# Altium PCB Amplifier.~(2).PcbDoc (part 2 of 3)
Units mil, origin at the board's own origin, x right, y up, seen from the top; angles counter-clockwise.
Board outline 9055.12 x 4724.41 mil, 2 copper layers (Top Layer, Bottom Layer); 154 components, 83 nets, 405 pads, 1525 vias.
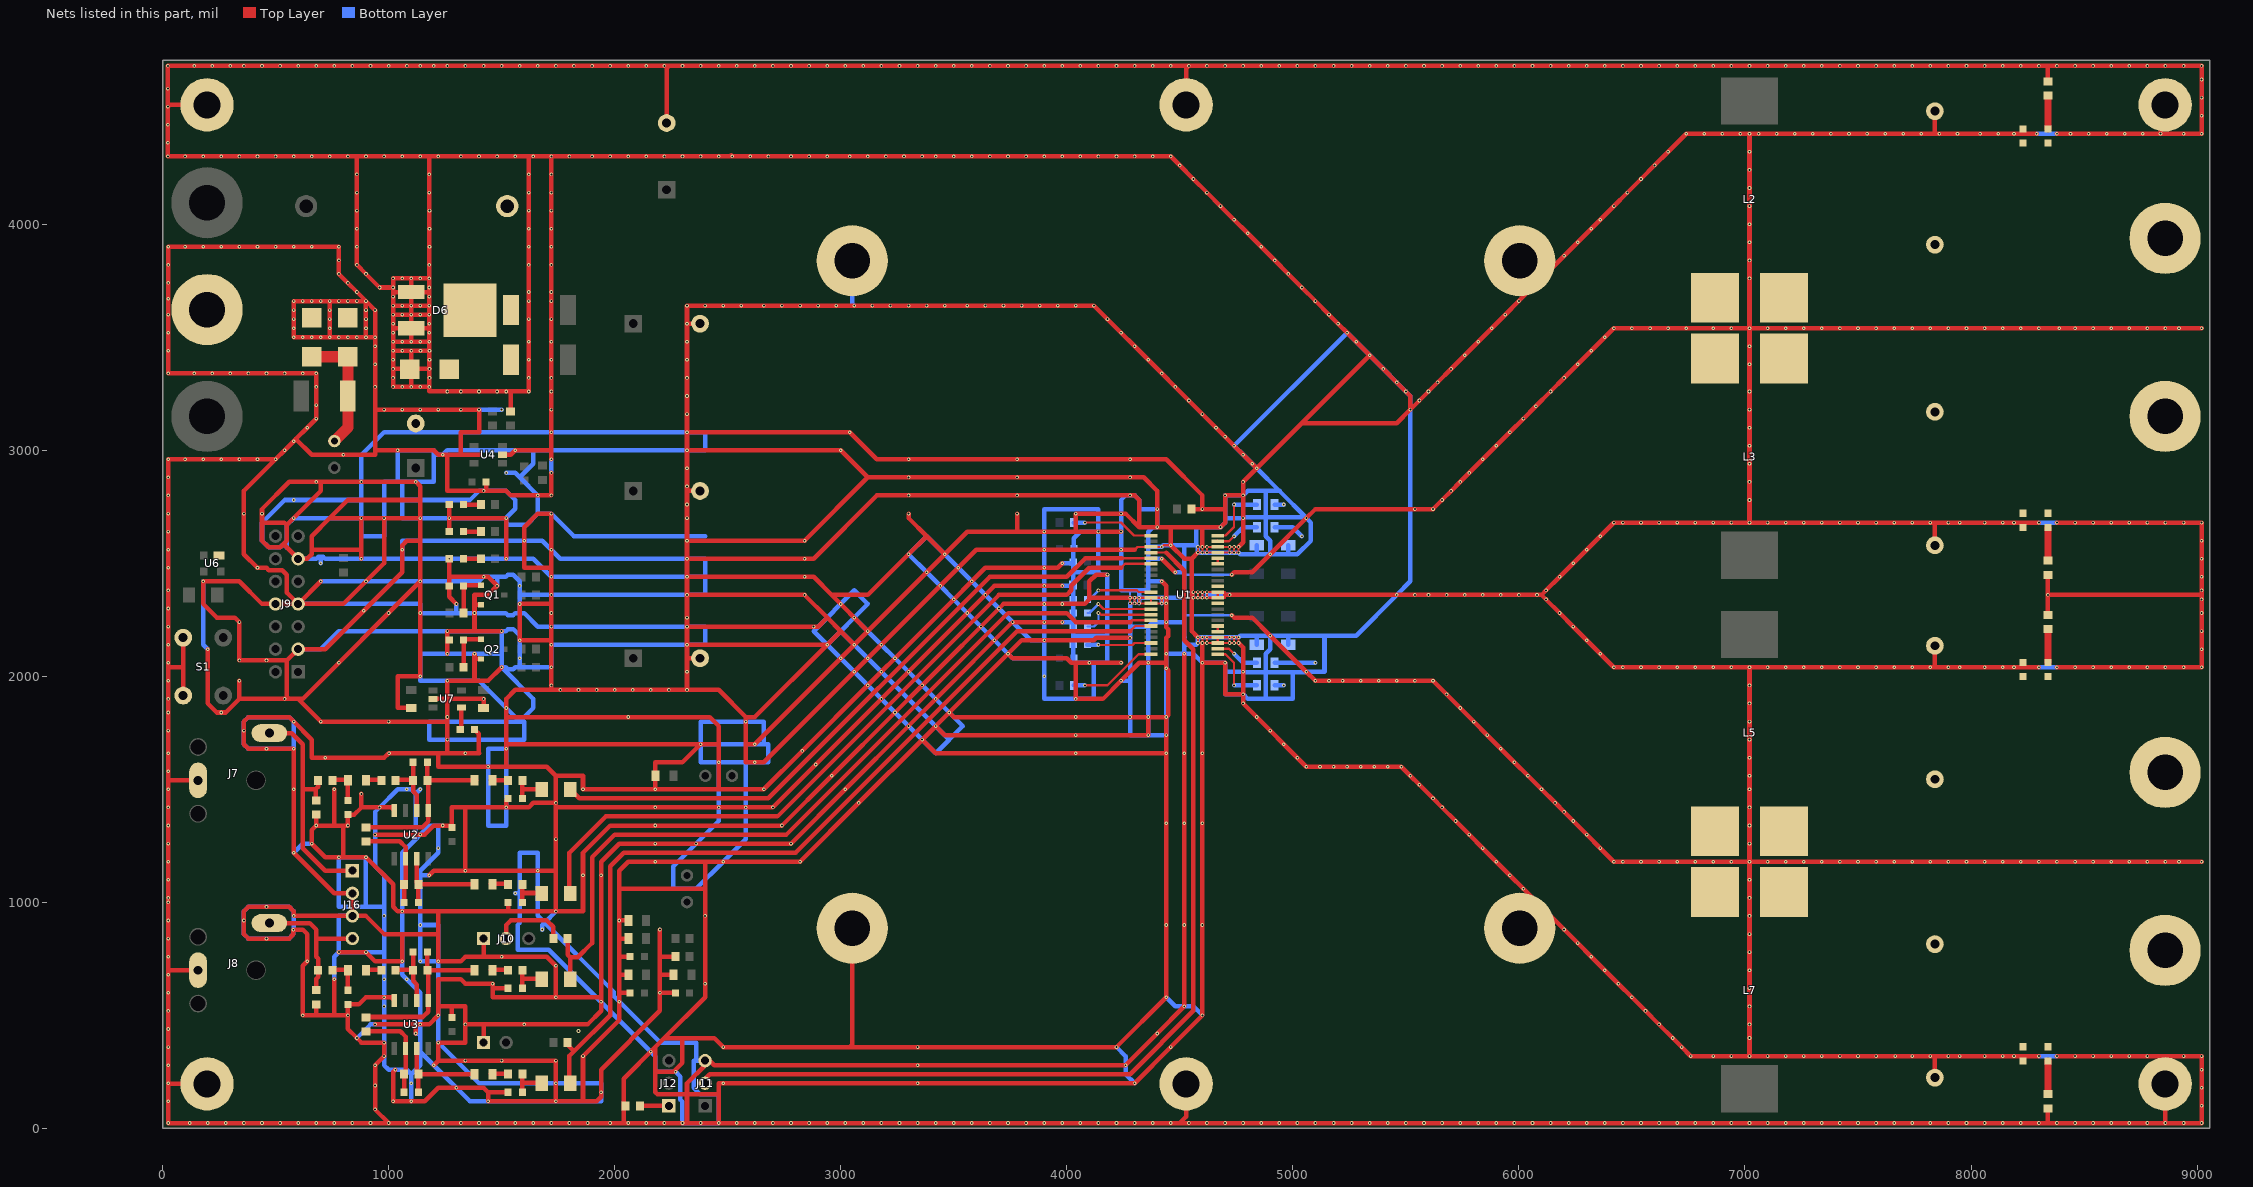
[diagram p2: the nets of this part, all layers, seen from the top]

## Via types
v1: diameter 15.75, hole 7.87, Top Layer to Bottom Layer, 1525 vias

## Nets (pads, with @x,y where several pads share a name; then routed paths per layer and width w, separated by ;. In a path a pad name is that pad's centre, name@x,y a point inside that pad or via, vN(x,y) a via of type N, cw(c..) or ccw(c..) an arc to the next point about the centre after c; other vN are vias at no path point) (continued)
GND: C4.2 C5.2 C6.2 C7.2 C8.2 C9.2 C10.2 C13.2 C14.2 C16.2 C17.2 C20.2 C21.2 C24.2 C25.2 C26.2 C28.2 C29.2 C30.2 C32.2 C33.2 C34.2 C35.2 C36.2 C37.2 C38.2 C39.2 C42.2 C44.1 C45.2 C46.2 C49.1 C50.2 C54.2 C55.2 C59.2 C60.2 C63.2 C65.2 C67.1 C68.2 C69.2 C72.2 C73.2 D1.2 D2.2 D3.2 D4.2 D5.2 D6.1 D6.3 D7.1 D8.1 D9.1 J2.1 J7.1 J8.1 J9.3 J9.7 J9.8 J9.11 J10.1 J11.3 J14.1 J16.2 J16.3 pad. Q1.3 Q2.3 R17.2 R25.2 R34.2 R39.2 R41.2 R46.2 R49.1 R51.2 R55.2 R57.1 R60.1 S1.1 U1.3 U1.12 U1.13 U1.25 U1.26 U1.33 U1.34 U1.41 U1.42 U2.4 U3.4 U4.2 U6.1 U7.2 | length 233486.2
  Top Layer w10: D5.2@1260,2528.5 v1(1268.5,2520) ; D4.2@1260,2648.5 D4.2@1268.5,2640 ; D3.2@1260,2751.5 D3.2@1268.5,2760 ; 4300,2560 4312.5,2572.5 U1.3@4372.36,2572.5 v1(4420,2572.5) 4427.5,2580 v1(4460,2580) ; v1(4440,2322.5) v1(4420,2322.5) ; v1(4440,2347.5) v1(4420,2347.5) ; v1(4300,2322.5) v1(4280,2322.5) v1(4280,2347.5) v1(4300,2347.5) ; v1(4300,2322.5) v1(4320,2322.5) ; v1(4300,2322.5) v1(4300,2347.5) ; v1(4300,2347.5) v1(4320,2347.5) ; v1(4320,2322.5) U1.13@4372.36,2322.5 ; v1(4320,2322.5) v1(4320,2347.5) ; v1(4320,2347.5) U1.12@4372.36,2347.5 ; U1.13@4372.36,2322.5 v1(4420,2322.5) ; U1.13@4372.36,2322.5 U1.12@4372.36,2347.5 ; U1.12@4372.36,2347.5 v1(4420,2347.5) ; v1(4420,2322.5) v1(4420,2347.5) ; v1(4580,2347.5) v1(4560,2347.5) v1(4560,2372.5) v1(4580,2372.5) ; v1(4580,2347.5) v1(4600,2347.5) ; v1(4580,2347.5) v1(4580,2372.5) ; v1(4580,2372.5) v1(4600,2372.5) ; v1(4600,2147.5) v1(4600,2172.5) ; v1(4600,2147.5) v1(4620,2147.5) ; v1(4600,2147.5) v1(4580,2147.5) v1(4580,2172.5) v1(4600,2172.5) ; v1(4600,2172.5) v1(4620,2172.5) ; v1(4600,2347.5) v1(4600,2372.5) ; v1(4600,2347.5) v1(4620,2347.5) ; v1(4600,2372.5) v1(4620,2372.5) ; v1(4600,2547.5) v1(4600,2572.5) ; v1(4600,2547.5) v1(4620,2547.5) ; v1(4600,2547.5) v1(4580,2547.5) v1(4580,2572.5) v1(4600,2572.5) ; v1(4600,2572.5) v1(4620,2572.5) ; v1(4620,2147.5) U1.25@4667.64,2147.5 ; v1(4620,2147.5) v1(4620,2172.5) ; v1(4620,2172.5) U1.26@4667.64,2172.5 ; v1(4620,2347.5) U1.33@4667.64,2347.5 ; v1(4620,2347.5) v1(4620,2372.5) ; v1(4620,2372.5) U1.34@4667.64,2372.5 ; v1(4620,2547.5) U1.41@4667.64,2547.5 v1(4720,2547.5) ; v1(4620,2547.5) v1(4620,2572.5) ; v1(4620,2572.5) U1.42@4667.64,2572.5 v1(4720,2572.5) ; U1.25@4667.64,2147.5 U1.26@4667.64,2172.5 ; U1.25@4667.64,2147.5 v1(4720,2147.5) ; U1.26@4667.64,2172.5 v1(4720,2172.5) ; U1.33@4667.64,2347.5 U1.34@4667.64,2372.5 ; U1.33@4667.64,2347.5 4700,2347.5 4700,2360 4700,2372.5 U1.34@4667.64,2372.5 ; v1(4720,2147.5) v1(4740,2147.5) ; v1(4720,2147.5) v1(4720,2172.5) ; v1(4720,2172.5) v1(4740,2172.5) ; v1(4720,2547.5) v1(4740,2547.5) ; v1(4720,2547.5) v1(4720,2572.5) ; v1(4720,2572.5) v1(4740,2572.5) ; v1(4740,2147.5) v1(4740,2172.5) ; v1(4740,2147.5) v1(4760,2147.5) v1(4760,2172.5) v1(4740,2172.5) ; v1(4740,2547.5) v1(4740,2572.5) ; v1(4740,2547.5) v1(4760,2547.5) v1(4760,2572.5) v1(4740,2572.5)
  Top Layer w20: S1.1@91.42,1915.1 91.42,2040 ; S1.1@91.42,2171 91.42,2040 ; J8.1@157.48,700 25.58,700 ; J7.1@157.48,1540 25.58,1540 ; pad.@193.7,200 pad.@196.85,196.85 28.73,196.85 v1(25.58,200) ; pad.@196.85,4527.56 31.56,4527.56 v1(24,4520) ; v1(200,2120) 200,1880 240,1840 280,1840 340,1900 ; v1(340,1980) 340,1900 ; R34.2@680,548.5 680,500 ; R17.2@680,1388.5 v1(680,1340) ; v1(700,2420) J9.7@600,2320 ; v1(760,660) 760,500 ; v1(760,1500) 760,1340 ; v1(780,780) v1(900,780) 940,740 v1(1060,740) 1060,860 ; v1(880,1480) 880,1420 ; v1(880,2520) 880,2560 ; v1(900,3500) v1(900,3660) ; v1(940,460) 1120,460 ; v1(940,1300) v1(1140,1300) 1160,1300 1200,1340 v1(1240,1340) 1271.5,1340 C5.2@1280,1331.5 ; v1(1020,3680) v1(1020,3640) ; U3.4@1025,566.3 1011.3,580 v1(980,580) 900,580 868.5,548.5 C24.2@820,548.5 v1(820,500) ; U2.4@1025,1406.3 1011.3,1420 v1(960,1420) 880,1420 ; v1(1030,260) 1020,250 v1(1020,120) v1(1100,120) 1160,120 1220,180 v1(1300,180) 1420,180 1440,160 ; C72.2@1100,1860.63 1099.37,1860 1040,1860 1040,2000 v1(1140,2000) v1(1140,2280) v1(1140,2420) ; v1(1120,420) 1120,460 ; 1139.5,2638.5 1139.5,2620 1140,2619.5 1140,2600 ; 1139.5,2640 v1@1139.5,2700 ; v1(1140,2700) v1@1139.5,2700 ; 1140,2780 820,2780 740,2700 ; v1(1180,1120) 1200,1140 v1(1340,1140) ; 1180,4300 v1(1180,3820) v1(1180,3760) ; v1(1181.01,3360) v1@1180,3360 ; U7.2@1197.01,1900 1260,1900 ; v1(1200,280) 1220,300 ; 1220,320 1220,300 ; 1259.84,2980 1259.84,2820 v1(1420,2820) 1520,2820 1540,2800 v1(1660,2800) v1(1720,2800) v1(1720,2900) ; v1(1260,2100) v1(1260,2200) 1380,2200 ; v1(1268.5,2520) 1268.5,2440 ; D4.2@1268.5,2640 v1(1268.5,2700) ; D3.2@1268.5,2760 v1(1268.5,2700) ; C21.2@1280,491.5 1280,540 ; C5.2@1280,1340 1280,1420 1340,1420 ; v1(1300,2320) 1268.5,2351.5 D1.2@1268.5,2400 1268.5,2440 ; v1(1380,2100) 1380,2076.69 ; C30.2@1380.04,1765 1399.37,1745.67 1399.37,1660.63 1400,1660 v1(1340,1660) 1260,1660 ; 1400,2980 1320,2980 ; Q2.3@1408.82,2076.69 1380,2076.69 ; Q1.3@1408.82,2316.69 1380,2316.69 ; J14.1@1420,380 1420,460 ; J10.1@1420,840 1420,760 ; C73.2@1420,1860.63 v1(1420,1900) 1260,1900 ; 1431.5,2828.5 C26.2@1431.5,2860 ; v1(1500,2040) 1440,1980 1380,1980 ; v1(1500,2200) 1380,2200 ; U4.2@1502.99,2980 1540,2980 v1(1560,3000) 1720,3000 ; v1(1520,2520) v1(1520,2700) v1(1268.5,2700) ; C25.2@1528.5,160 1440,160 ; C20.2@1528.5,620 1460,620 ; C14.2@1528.5,1000 1528.5,968.5 1520,960 ; C4.2@1528.5,1460 1520,1451.5 v1(1520,1420) ; R39.2@1540,3171.5 1540,3260 ; v1(1720,2960) 1720,3000 ; 1740,1420 v1(2180,1420) v1(2700,1420) v1(2890,1610) v1(3180,1900) v1(3300,2020) 3680,2400 v1(3900,2400) v1(3980,2400) ; 2040,24 2040,220 2180,360 ; C9.2@2060.63,680 2020,680 ; C7.2@2060.63,840 2020,840 ; C6.2@2060.63,920 v1(2020,920) ; C10.2@2068.5,600 2020,600 ; C8.2@2068.5,760 2020,760 ; C59.2@2180.63,1560 C59.2@2180,1559.37 ; v1(2200,880) 2200,760 ; C32.2@2230,4447.64 2230,4690 2240,4700 ; C16.2@2260.63,680 2200,680 ; C17.2@2268.5,600 v1(2200,600) ; R25.2@2268.5,760 2200,760 ; C33.2@2377.64,2080 2320,2080 ; C34.2@2377.64,2820 2320,2820 ; C35.2@2377.64,3560 v1(2320,3560) ; J11.3@2380,300 J11.3@2400,300 ; v1@2515.43,4304.57 v1(2520,4300) ; pad.@3045.35,880 pad.@3051.18,885.83 3051.18,371.18 3040,360 ; pad.@3051.18,3838.58 pad.@3060,3847.4 ; v1(3300,2720) 3300,2700 3380,2620 ; v1(3420,1780) 3460,1740 v1(4040,1740) v1(4360,1740) v1(4360,1820) ; v1(3780,2720) 3780,2640 ; v1(3980,2240) v1(3900,2240) v1(3760,2240) v1(3420,1900) v1(3300,1780) v1(3020,1500) v1(2780,1260) v1(2180,1260) 2020,1260 1940,1180 1940,580 ; v1(3980,2500) 3960,2480 v1(3900,2480) 3640,2480 v1(3580,2420) v1(3500,2340) v1(3240,2080) v1(3180,2020) v1(3120,1960) v1(2830,1670) v1(2660,1500) 2460,1500 ; v1(4180,2450) 4130,2450 4100,2420 4100,2340 ; v1(4240,2060) v1(4100,2060) 4040,2060 ; v1(4240,2640) v1(4140,2640) 4040,2640 ; v1(4280,2170) 4130,2170 4120,2160 v1(3901.01,2160) 3800,2160 v1(3740,2100) ; v1(4280,2347.5) 4279.63,2347.87 4107.87,2347.87 4100,2340 ; 4300,2560 v1(4240,2560) v1(3900,2560) 3600,2560 v1(3520,2480) v1(3440,2400) v1(3180,2140) v1(3120,2080) v1(3060,2020) 2660,1620 v1(2620,1620) 2580,1620 2580,1700 ; v1(4420,2420) 4440,2400 v1(4440,2347.5) v1(4440,2322.5) v1(4440,2240) 4440,2216.92 4447.87,2209.05 4447.87,2178.08 4440,2170.21 v1(4440,2100) 4440,2060 ; v1(4420,2520) v1(4480,2460) ; pad.@4460,4460 pad.@4527.56,4527.56 4527.56,4687.56 v1(4540,4700) ; pad.@4503.15,196.85 pad.@4527.56,196.85 4527.56,51.56 4500,24 ; v1(4520,2100) v1(4520,1350) v1(4520,900) v1(4520,540) v1(4400,420) v1(4260,280) v1(3340,280) 2440,280 2420,300 J11.3@2400,300 ; R60.1@4551.5,2740 v1(4600,2740) ; v1(4580,2172.5) 4552.13,2200.37 4552.13,2519.63 ; v1(4580,2547.5) 4552.13,2519.63 ; v1(4600,2147.5) v1(4600,2060) ; v1(4600,2572.5) 4600,2660 ; 4700,2360 v1(4720,2360) v1(5460,2360) v1(5540,2360) v1(5600,2360) v1(5680,2360) v1(5760,2360) v1(5840,2360) v1(5920,2360) v1(6000,2360) v1(6080,2360) 6100,2360 ; v1(4730,2270) 4740,2260 4820,2260 v1(4900,2180) v1(5060,2020) v1(5100,1980) v1(5160,1980) v1(5220,1980) v1(5300,1980) v1(5380,1980) v1(5460,1980) v1(5540,1980) v1(5620,1980) v1(5680,1920) v1(5740,1860) v1(5800,1800) v1(5860,1740) v1(5920,1680) v1(5980,1620) v1(6040,1560) v1(6100,1500) v1(6160,1440) v1(6200,1400) v1(6240,1360) v1(6300,1300) v1(6360,1240) v1(6420,1180) v1(6460,1180) v1(6540,1180) v1(6620,1180) v1(6700,1180) v1(6780,1180) v1(6860,1180) v1(6940,1180) v1(7020,1180) ; v1(4730,2450) 4740,2460 4820,2460 v1(4900,2540) v1(5060,2700) 5100,2740 v1(5540,2740) v1(5620,2740) v1(5660,2780) v1(5700,2820) v1(5740,2860) v1(5780,2900) v1(5840,2960) v1(5900,3020) v1(5960,3080) v1(6020,3140) v1(6075,3195) v1(6140,3260) v1(6200,3320) v1(6260,3380) v1(6320,3440) v1(6380,3500) v1(6420,3540) v1(6500,3540) v1(6580,3540) v1(6660,3540) v1(6740,3540) v1(6860,3540) v1(6940,3540) v1(7020,3540) ; v1(4760,2147.5) 4780,2127.5 v1(4780,2020) v1(4780,1920) ; v1(4760,2572.5) 4780,2592.5 v1(4780,2700) v1(4780,2800) ; pad.@6003.94,885.83 6005.83,885.83 pad.@6100,980 ; v1@7815,2040 v1(7740,2040) v1(7660,2040) v1(7580,2040) v1(7500,2040) v1(7420,2040) v1(7340,2040) v1(7260,2040) v1(7180,2040) v1(7100,2040) v1(7020,2040) ; v1(7820,2040) 7840,2040 ; C68.2@7840,224.72 7840,320 ; C54.2@7840,2160 C54.2@7840,2135.28 7840,2040 ; C28.2@7840,4500 7840,4400 ; C45.2@7840.28,2579.72 7840.28,2680 ; v1(8290,4400) v1(8190,4400) v1(8120,4400) v1(8040,4400) v1(7940,4400) v1(7860,4400) 7840,4400 ; v1(8300,320) v1(8190,320) v1(8140,320) v1(8060,320) v1(7950,320) v1(7900,320) 7840,320 ; v1(8300,2040) v1(8190,2040) v1(8140,2040) v1(8060,2040) v1(7950,2040) v1(7900,2040) 7840,2040 ; v1(8300,2680) v1(8190,2680) v1(8140,2680) v1(8060,2680) v1(7950,2680) v1(7900,2680) 7840.28,2680 ; R55.2@8340,88.5 8340,24 ; R51.2@8340,2280 v1(8340,2360) ; R46.2@8340,2448.5 v1(8340,2360) ; R41.2@8340,4631.5 8340,4700 ; v1(8380,320) v1(8460,320) v1(8540,320) v1(8620,320) v1(8700,320) v1(8780,320) v1(8940,320) v1(9020,320) v1(9020,260) v1(9020,180) v1(9020,100) v1(9020,24) v1(8940,24) v1(8860,24) ; v1(8380,2040) v1(8460,2040) v1(8540,2040) v1(8620,2040) v1(8700,2040) v1(8780,2040) v1(8860,2040) v1(8940,2040) v1(9020,2040) v1(9020,2120) v1(9020,2200) v1(9020,2280) v1(9020,2340) 9020,2360 ; v1(8380,2680) v1(8460,2680) v1(8540,2680) v1(8620,2680) v1(8700,2680) v1(8780,2680) v1(8860,2680) v1(8940,2680) v1(9020,2680) v1(9020,2600) v1(9020,2520) v1(9020,2440) v1(9020,2380) 9020,2360 ; v1(8380,4400) v1(8440,4400) v1(8520,4400) v1(8600,4400) v1(8680,4400) v1(8760,4400) v1(8940,4400) v1(9020,4400) v1(9020,4480) v1(9020,4560) v1(9020,4640) v1(9020,4700) v1(8940,4700) v1(8860,4700) v1(8780,4700) v1(8700,4700) v1(8620,4700) v1(8540,4700) v1(8460,4700) v1(8380,4700) 8340,4700 ; v1(8838.16,4400.63) 8838.16,4507.46 pad.@8858.27,4527.56 ; pad.@8858.27,196.85 8858.27,25.73 v1(8860,24) ; v1(9020,1180) v1(8920,1180) v1(8860,1180) v1(8780,1180) v1(8700,1180) v1(8620,1180) v1(8540,1180) v1(8460,1180) v1(8380,1180) v1(8300,1180) v1(8220,1180) v1(8140,1180) v1(8060,1180) v1(7980,1180) v1(7900,1180) v1(7820,1180) v1(7740,1180) v1(7660,1180) v1(7580,1180) v1(7500,1180) v1(7420,1180) v1(7340,1180) v1(7260,1180) v1(7180,1180) v1(7100,1180) v1(7020,1180) ; v1(9020,3540) v1(8920,3540) v1(8860,3540) v1(8780,3540) v1(8700,3540) v1(8620,3540) v1(8540,3540) v1(8460,3540) v1(8390,3540) v1(8300,3540) v1(8220,3540) v1(8140,3540) v1(8060,3540) v1(7980,3540) v1(7900,3540) v1(7820,3540) v1(7740,3540) v1(7660,3540) v1(7580,3540) v1(7500,3540) v1(7420,3540) v1(7340,3540) v1(7260,3540) v1(7180,3540) v1(7100,3540) v1(7020,3540) ; v1(24,4520) v1(24,4440) v1(24,4360) v1(24,4300) v1(100,4300) v1(180,4300) v1(260,4300) v1(340,4300) v1(420,4300) v1(500,4300) v1(580,4300) v1(660,4300) v1(740,4300) v1(820,4300) 860,4300 ; v1(24,4520) v1(24,4600) v1(24,4700) v1(140,4700) v1(220,4700) v1(300,4700) v1(360,4700) v1(440,4700) v1(520,4700) v1(600,4700) v1(680,4700) v1(1140,4700) v1(1200,4700) v1(1260,4700) v1(1340,4700) v1(1420,4700) v1(1500,4700) v1(1580,4700) v1(1660,4700) v1(1740,4700) v1(1820,4700) v1(1900,4700) v1(1980,4700) v1(2060,4700) v1(2140,4700) v1(2220,4700) 2240,4700 ; v1(25.58,200) v1(25.58,280) v1(25.58,360) v1(25.58,440) v1(25.58,520) v1(25.58,600) v1(25.58,680) 25.58,700 ; v1(25.58,200) v1(25.58,120) v1(25.58,24) v1(120,24) v1(200,24) v1(280,24) v1(360,24) v1(440,24) v1(520,24) v1(600,24) v1(680,24) v1(760,24) v1(840,24) v1(920,24) v1(1000,24) ; 25.58,700 v1(25.58,760) v1(25.58,840) v1(25.58,920) v1(25.58,1000) v1(25.58,1100) v1(25.58,1180) v1(25.58,1260) v1(25.58,1340) v1(25.58,1420) v1(25.58,1500) 25.58,1540 ; 25.58,1540 v1(25.58,1580) v1(25.58,1660) v1(25.58,1760) v1(25.58,1840) v1(25.58,1900) v1(25.58,1980) 25.58,2040 ; 25.58,2040 91.42,2040 ; 25.58,2040 v1(25.58,2060) v1(25.58,2140) v1(25.58,2220) v1(25.58,2300) v1(25.58,2380) v1(25.58,2480) v1(25.58,2560) v1(25.58,2640) v1(25.58,2720) v1(25.58,2800) v1(25.58,2880) v1(25.58,2960) v1(100,2960) v1(180,2960) v1(260,2960) v1(340,2960) v1(420,2960) v1(500,2960) ; 340,1900 v1(540,1900) 560,1900 ; 440,2680 539.06,2680 549.53,2669.53 ; 440,2680 440,2600 469.53,2570.47 520.52,2570.47 530.04,2580 ; 440,2680 440,2740 560,2860 700,2860 ; v1(500,2960) v1(540,3000) v1(580,3040) 590,3050 ; v1(500,2960) 360,2820 360,2540 v1(420,2480) 460,2480 470.47,2469.53 529.46,2469.53 549.53,2449.46 549.53,2420.94 550.47,2420 550.47,2369.53 J9.7@600,2320 ; 530.04,2580 540,2580 J9.11@600,2520 640,2520 643.13,2523.13 643.13,2523.56 660,2540.43 660,2560 ; 530.04,2580 549.53,2599.48 549.53,2669.53 ; 549.53,2669.53 700,2820 700,2860 ; 550.47,2070.47 J9.3@600,2120 720,2120 v1(890,2290) 1060,2460 1060,2578.99 1081.01,2600 1140,2600 ; 550.47,2070.47 550.47,1909.53 560,1900 ; 550.47,2070.47 v1(460,2070.47) v1(340,2070.47) v1(340,2240) 320,2260 240,2260 180,2320 v1(180,2420) 340,2420 440,2320 J9.8@500,2320 J9.7@600,2320 ; 560,1900 600,1900 ; 590,3050 660,2980 940,2980 940,3000 ; 590,3050 v1(640,3100) v1(680,3140) v1(680,3340) v1(140,3340) v1(25.58,3340) v1(25.58,3440) v1(25.58,3600) v1(25.58,3670) v1(25.58,3740) v1(25.58,3820) v1(25.58,3900) v1(100,3900) v1(180,3900) v1(260,3900) v1(340,3900) v1(420,3900) v1(500,3900) v1(780,3900) v1(780,3780) v1(900,3660) ; 600,1900 v1(700,1800) 1260,1800 ; 600,1900 620,1900 v1(1140,2420) ; J9.7@600,2320 800,2320 v1(900,2420) 980,2500 v1(980,2700) ; 660,2560 880,2560 ; 660,2560 660,2620 740,2700 ; 680,500 v1(620,500) 620,720 v1(640,740) 640,860 621.1,878.9 v1(578.9,878.9) 578.9,858.9 560,840 v1(460,840) 380,840 360,860 v1(360,920) 360,960 380,980 v1(460,980) 560,980 580,960 v1(580,940) J16.3@840,940 ; 680,500 760,500 ; v1(680,1340) 660,1320 v1(660,1260) 720,1200 v1(780,1200) 800,1200 ; v1(680,1340) 760,1340 ; 700,2860 v1(1120,2860) 1121.01,2860 1139.5,2841.51 v1@1139.5,2700 ; 740,2700 v1(880,2700) ; v1(740,3500) v1(740,3660) ; v1(740,3500) v1(580,3500) v1(580,3660) v1(740,3660) ; v1(740,3500) v1(940,3500) ; v1(740,3660) v1(900,3660) ; 760,500 v1(820,500) ; 760,1340 800,1340 ; 800,1200 800,1340 ; 800,1200 v1(900,1200) 1020,1080 1020,980 1040,960 v1(1060,960) 1219.5,960 ; 800,1340 v1(820,1340) C13.2@820,1388.5 848.5,1388.5 880,1420 ; v1(820,500) 820,440 v1(860,400) 880,380 v1(980,380) v1(980,320) v1(940,280) v1(940,190) v1(940,84) v1(1000,24) ; J16.3@840,940 J16.2@840,1040 760,1040 v1(580,1220) v1(580,1500) v1(580,1680) v1(460,1680) 380,1680 360,1700 v1(360,1760) 360,1800 380,1820 560,1820 v1(580,1800) 660,1720 660,1640 v1(720,1640) 980,1640 1000,1660 v1(1002.2,1660) 1220,1660 ; J16.3@840,940 900,940 980,860 1219.5,860 ; 860,4300 v1(860,4220) v1(860,4140) v1(860,4060) v1(860,3980) v1(860,3900) v1(860,3820) v1(900,3780) v1(960,3720) v1(1020,3720) ; 860,4300 v1(900,4300) v1(980,4300) v1(1060,4300) v1(1140,4300) v1(1220,4300) v1(1320,4300) v1(1400,4300) v1(1480,4300) v1(1560,4300) 1620,4300 ; 880,2560 v1(880,2700) ; v1(880,2700) v1(980,2700) ; v1(900,3660) v1(940,3620) v1(940,3500) ; 940,3000 1200,3000 1220,2980 1320,2980 ; 940,3000 940,3180 ; 940,3180 v1(980,3180) v1(1060,3180) v1(1140,3180) v1(1220,3180) v1(1320,3180) v1(1400,3180) 1400,3080 1320,3080 1320,2980 ; 940,3180 v1(940,3280) v1(940,3380) v1(940,3460) v1(940,3500) ; v1(980,2700) v1@1139.5,2700 ; v1(1000,24) v1(1080,24) v1(1160,24) v1(1240,24) v1(1320,24) v1(1400,24) v1(1480,24) v1(1560,24) v1(1640,24) v1(1720,24) v1(1800,24) v1(1880,24) v1(1980,24) v1(2060,24) v1(2140,24) v1(2220,24) v1(2300,24) 2320,24 ; v1(1020,3360) v1(1020,3320) v1(1020,3280) v1(1060,3280) v1(1100,3280) ; v1(1020,3360) v1(1020,3400) v1(1020,3440) ; v1(1020,3360) D7.1@1101.01,3360 ; v1(1020,3440) v1(1020,3480) ; v1(1020,3440) v1(1061.01,3440) v1(1101.01,3440) ; v1(1020,3480) v1(1060,3480) v1(1100,3480) ; v1(1020,3480) v1(1020,3520) 1020,3540 ; 1020,3540 D6.3@1100,3540 ; 1020,3540 v1(1020,3560) v1(1020,3600) ; v1(1020,3600) v1(1020,3640) ; v1(1020,3600) v1(1060,3600) v1(1100,3600) ; v1(1020,3640) v1(1060,3640) v1(1100,3640) ; v1(1020,3640) v1(1020,3720) ; v1(1020,3720) v1(1020,3760) v1(1060,3760) v1(1100,3760) ; v1(1020,3720) 1020,3700 D6.1@1100,3700 ; v1(1100,3280) v1(1140,3280) v1(1180,3280) ; v1(1100,3280) 1101.01,3281.01 D7.1@1101.01,3360 ; v1(1100,3480) v1(1140,3480) v1(1180,3480) ; v1(1100,3480) D6.3@1100,3540 ; D6.3@1100,3540 1180,3540 ; D6.3@1100,3540 v1(1100,3600) ; v1(1100,3600) v1(1100,3640) ; v1(1100,3600) v1(1140,3600) v1(1180,3600) ; v1(1100,3640) D6.1@1100,3700 ; v1(1100,3640) v1(1140,3640) v1(1180,3640) ; D6.1@1100,3700 v1(1100,3760) ; D6.1@1100,3700 1180,3700 ; v1(1100,3760) v1(1140,3760) v1(1180,3760) ; D7.1@1101.01,3360 v1@1180,3360 ; D7.1@1101.01,3360 v1(1101.01,3440) ; v1(1101.01,3440) v1(1141.01,3440) v1@1180,3440 ; 1120,460 v1(1140,460) 1180,460 v1(1220,500) 1220,540 ; v1(1140,2420) 1140,2600 ; v1(1180,3280) 1180,3260 v1(1620,3260) 1620,4300 ; v1(1180,3280) v1@1180,3360 ; v1@1180,3360 v1@1180,3440 ; v1@1180,3440 v1(1180,3480) ; v1(1180,3480) v1(1180,3520) 1180,3540 ; 1180,3540 v1(1180,3560) v1(1180,3600) ; v1(1180,3600) v1(1180,3640) ; v1(1180,3640) v1(1180,3680) 1180,3700 ; 1180,3700 v1(1180,3720) v1(1180,3760) ; 1219.5,860 1220,860 v1(1220,740) 1320,740 1340,760 1420,760 ; 1219.5,860 1219.5,960 ; 1219.5,960 1520,960 ; 1220,300 v1(1220,380) 1340,380 v1(1340,460) ; 1220,300 v1(1340,300) v1(1740,300) v1(1740,200) v1(1740,120) ; 1220,540 1280,540 ; 1220,540 1220,660 1320,660 1340,640 v1(1460,640) 1460,620 ; 1220,1660 1220,1600 v1(1440,1600) 1520,1600 ; 1220,1660 1260,1660 ; 1260,1660 1260,1800 ; 1260,1800 1260,1900 ; 1260,1900 v1(1260,1980) 1380,1980 ; 1268.5,2440 v1(1420,2440) 1440,2440 v1(1480,2400) 1440,2360 1380,2360 1380,2316.69 ; 1280,540 1340,540 v1(1340,460) ; v1(1340,460) 1420,460 ; v1(1340,1140) 1340,1420 ; v1(1340,1140) 1740,1140 ; 1340,1420 v1(1520,1420) ; 1380,1980 1380,2076.69 ; 1380,2200 1380,2316.69 ; 1420,460 1880,460 1940,520 1940,580 ; 1420,760 v1(1500,760) 1700,760 v1(1740,720) v1(1740,580) ; 1440,160 v1(1440,120) v1(1740,120) ; 1460,620 1460,580 v1(1740,580) ; 1520,960 v1(1740,960) ; v1(1520,1420) 1620,1420 1640,1440 v1(1740,1440) ; 1520,1600 1700,1600 1740,1560 ; 1520,1600 v1(1520,1680) 1520,1700 ; 1520,1700 v1(2380,1700) ; 1520,1700 1520,1820 ; 1520,1820 2420,1820 2460,1780 2460,1700 ; 1520,1820 1520,1900 1560,1940 1720,1940 ; 1620,4300 v1(1640,4300) v1(1720,4300) ; 1720,1940 v1(1720,1960) v1(1720,2040) v1(1720,2140) 1720,2160 ; 1720,1940 v1(1760,1940) v1(1840,1940) v1(1920,1940) v1(2000,1940) v1(2080,1940) v1(2160,1940) v1(2240,1940) v1(2320,1940) ; 1720,2160 v1(1580,2160) v1(1580,2320) 1720,2320 ; 1720,2160 v1(1720,2220) v1(1720,2280) 1720,2320 ; 1720,2320 v1(1720,2360) v1(1720,2440) 1720,2480 ; 1720,2480 1600,2480 v1(1600,2600) 1600,2660 1660,2720 v1(1720,2720) v1(1720,2560) 1720,2480 ; 1720,3000 v1(1720,3080) v1(1720,3180) v1(1720,3260) v1(1720,3320) v1(1720,3400) v1(1720,3480) v1(1720,3580) v1(1720,3660) v1(1720,3700) v1(1720,3820) v1(1720,3900) v1(1720,3980) v1(1720,4060) v1(1720,4140) v1(1720,4220) v1(1720,4300) ; v1(1720,4300) v1(1800,4300) v1(1900,4300) v1(1980,4300) v1(2060,4300) v1(2140,4300) v1(2220,4300) v1(2300,4300) v1(2380,4300) v1(2460,4300) v1(2520,4300) ; v1(1740,120) 1860,120 ; v1(1740,580) 1940,580 ; v1(1740,960) 1860,960 1860,1220 1980,1340 v1(2180,1340) v1(2740,1340) v1(2960,1560) v1(3240,1840) v1(3360,1960) 3720,2320 v1(3900,2320) v1(3980,2320) 4080,2320 4100,2340 ; v1(1740,960) 1740,1140 ; 1740,1140 v1(1740,1280) v1(1740,1440) ; v1(1740,1440) 1740,1560 ; 1740,1560 1860,1560 v1(1860,1500) v1(2180,1500) ; 1860,120 v1(1860,320) 2020,480 2020,600 ; 1860,120 1920,120 1940,140 v1(1940,160) 1940,260 2200,520 v1(2200,600) ; 2020,600 2020,680 ; 2020,680 2020,760 ; 2020,760 2020,840 ; 2020,840 v1(2020,920) ; v1(2020,920) 2020,1060 ; 2020,1060 2400,1060 ; 2020,1060 2020,1140 2060,1180 v1(2180,1180) 2400,1180 ; 2180,260 2189.53,250.47 2260.52,250.47 2300,289.96 2300,400 ; 2180,260 2180,160 2189.53,150.47 2320,150.47 ; 2180,260 2180,360 ; 2180,360 2220,400 ; v1(2180,1500) C59.2@2180,1559.37 ; v1(2180,1500) 2460,1500 ; C59.2@2180,1559.37 2180,1620 2300,1620 v1(2380,1700) ; v1(2200,600) 2200,680 ; 2200,680 2200,760 ; 2220,400 2400,580 v1(2400,640) 2400,1060 ; 2220,400 2300,400 ; 2240,4700 v1(2300,4700) v1(2380,4700) v1(2460,4700) v1(2540,4700) v1(2620,4700) v1(2700,4700) v1(2780,4700) v1(2860,4700) v1(2940,4700) v1(3020,4700) v1(3100,4700) v1(3180,4700) v1(3260,4700) v1(3340,4700) v1(3420,4700) v1(3500,4700) v1(3580,4700) v1(3660,4700) v1(3740,4700) v1(3820,4700) v1(3900,4700) v1(3980,4700) v1(4060,4700) v1(4140,4700) v1(4220,4700) v1(4300,4700) v1(4380,4700) v1(4460,4700) v1(4540,4700) ; 2300,400 2440,400 v1(2480,360) 3040,360 ; 2320,24 2320,150.47 ; 2320,24 v1(2380,24) v1(2460,24) ; 2320,150.47 2460,150.47 ; 2320,150.47 2320,200 2400,280 J11.3@2400,300 ; v1(2320,1940) v1(2320,2020) 2320,2080 ; v1(2320,1940) 2460,1940 2580,1820 ; 2320,2080 v1(2320,2140) ; v1(2320,2140) v1(2320,2220) ; v1(2320,2140) v1(2940,2140) ; v1(2320,2220) v1(2320,2260) v1(2320,2360) ; v1(2320,2220) 2900,2220 2940,2260 ; v1(2320,2360) v1(2320,2440) ; v1(2320,2360) v1(2840,2360) 2940,2260 ; v1(2320,2440) 2880,2440 2960,2360 ; v1(2320,2440) v1(2320,2520) ; v1(2320,2520) 2880,2520 3160,2800 v1(4280,2800) 4300,2800 4320,2780 4320,2660 ; v1(2320,2520) v1(2320,2600) ; v1(2320,2600) v1(2320,2700) v1(2320,2760) 2320,2820 ; v1(2320,2600) v1(2840,2600) 3120,2880 ; 2320,2820 v1(2320,2840) v1(2320,2920) v1(2320,3000) ; v1(2320,3000) v1(2320,3080) ; v1(2320,3000) v1(3000,3000) 3120,2880 ; v1(2320,3080) v1(2320,3160) v1(2320,3240) v1(2320,3320) v1(2320,3400) v1(2320,3480) v1(2320,3560) ; v1(2320,3080) v1(3040,3080) 3160,2960 v1(4280,2960) 4440,2960 4600,2800 v1(4600,2740) ; v1(2320,3560) v1(2320,3640) v1(2660,3640) v1(2740,3640) v1(2820,3640) v1(2900,3640) v1(2980,3640) v1(3060,3640) v1(3140,3640) v1(3220,3640) v1(3300,3640) v1(3380,3640) v1(3460,3640) v1(3560,3640) v1(3640,3640) v1(3720,3640) v1(3800,3640) v1(3880,3640) v1(3960,3640) v1(4040,3640) v1(4120,3640) v1(4180,3580) v1(4240,3520) v1(4300,3460) v1(4360,3400) v1(4420,3340) v1(4480,3280) v1(4540,3220) v1(4600,3160) v1(4660,3100) v1(4700,3060) v1(4740,3020) v1(4780,2980) v1(4820,2940) v1(4840,2920) ; v1(2380,1700) 2460,1700 ; 2400,1060 2400,1180 ; 2400,1180 v1(2820,1180) v1(3080,1440) v1(3360,1720) ; v1(2460,24) v1(2540,24) v1(2620,24) v1(2700,24) v1(2780,24) v1(2860,24) v1(2940,24) v1(3020,24) v1(3100,24) v1(3180,24) v1(3260,24) v1(3340,24) v1(3420,24) v1(3500,24) v1(3580,24) v1(3660,24) v1(3740,24) v1(3820,24) v1(3900,24) v1(3980,24) v1(4060,24) v1(4140,24) v1(4220,24) v1(4300,24) v1(4380,24) v1(4460,24) 4500,24 ; v1(2460,24) 2460,150.47 ; 2460,150.47 2460,200 v1(3340,200) v1(4300,200) v1(4460,360) v1(4600,500) v1(4600,900) v1(4600,1350) v1(4600,1660) v1(4600,2060) ; 2460,1500 v1(2460,1620) 2460,1700 ; v1(2520,4300) v1(2600,4300) v1(2680,4300) v1(2780,4300) v1(2860,4300) v1(2940,4300) v1(3040,4300) v1(3120,4300) v1(3200,4300) v1(3280,4300) v1(3420,4300) v1(3500,4300) v1(3580,4300) v1(3660,4300) v1(3740,4300) v1(3820,4300) v1(3900,4300) v1(3980,4300) v1(4060,4300) v1(4140,4300) v1(4220,4300) v1(4300,4300) v1(4380,4300) v1(4460,4300) v1(4500,4260) v1(4560,4200) v1(4620,4140) v1(4680,4080) v1(4740,4020) v1(4800,3960) v1(4860,3900) v1(4920,3840) v1(4980,3780) v1(5040,3720) v1(5100,3660) v1(5160,3600) v1(5200,3560) v1(5240,3520) v1(5280,3480) v1(5340,3420) ; 2580,1700 v1(2620,1700) v1(3000,2080) v1(3060,2140) ; 2580,1700 2580,1820 ; 2580,1820 2620,1820 v1(2940,2140) ; v1(2940,2140) 3000,2200 ; 2940,2260 3000,2200 ; 2960,2360 3120,2360 v1(3300,2540) 3380,2620 ; 2960,2360 v1(3120,2200) ; 3000,2200 v1(3060,2140) ; 3040,360 v1(3340,360) v1(4220,360) v1(4440,580) v1(4440,900) v1(4440,1350) v1(4440,1660) ; v1(3060,2140) v1(3120,2200) ; v1(3120,2200) v1(3380,2460) v1(3460,2540) ; 3120,2880 v1(4280,2880) 4340,2880 4400,2820 v1(4400,2740) v1(4400,2660) ; v1(3360,1720) v1(3480,1840) ; v1(3360,1720) 3420,1660 v1(4040,1660) v1(4440,1660) ; 3380,2620 v1(3460,2540) ; v1(3460,2540) 3560,2640 3780,2640 ; v1(3480,1840) v1(3740,2100) ; v1(3480,1840) 3500,1820 v1(4040,1820) v1(4280,1820) v1(4360,1820) ; v1(3740,2100) 3760,2080 4000,2080 4020,2060 4040,2060 ; 3780,2640 v1(3900,2640) 4040,2640 ; 4040,2060 v1(4040,1900) 4160,1900 v1(4240,1980) 4320,2060 v1(4360,2060) 4440,2060 ; 4040,2640 v1(4040,2720) 4260,2720 4320,2660 ; 4320,2660 v1(4400,2660) ; v1(4360,1820) v1(4440,1820) ; v1(4400,2660) 4460,2660 ; v1(4440,1660) v1(4440,1740) v1(4440,1820) ; v1(4440,1820) 4448.21,1828.21 4448.21,2027.56 v1(4440,2035.77) 4440,2060 ; 4460,2660 v1(4460,2580) 4520.37,2519.63 4552.13,2519.63 ; 4460,2660 4600,2660 ; 4500,24 v1(4540,24) v1(4620,24) v1(4700,24) v1(4780,24) v1(4860,24) v1(4940,24) v1(5020,24) v1(5100,24) v1(5180,24) v1(5260,24) v1(5340,24) v1(5420,24) v1(5500,24) v1(5580,24) v1(5660,24) v1(5740,24) v1(5820,24) v1(5900,24) v1(5980,24) v1(6060,24) v1(6140,24) v1(6220,24) v1(6300,24) v1(6380,24) v1(6460,24) v1(6540,24) v1(6620,24) v1(6700,24) v1(6780,24) v1(6860,24) v1(6940,24) v1(7020,24) v1(7100,24) v1(7180,24) v1(7260,24) v1(7340,24) v1(7420,24) v1(7500,24) v1(7580,24) v1(7660,24) v1(7740,24) v1(7820,24) v1(7900,24) v1(7980,24) v1(8060,24) v1(8140,24) v1(8220,24) v1(8300,24) 8340,24 ; v1(4540,4700) v1(4620,4700) v1(4700,4700) v1(4780,4700) v1(4860,4700) v1(4940,4700) v1(5020,4700) v1(5100,4700) v1(5180,4700) v1(5260,4700) v1(5340,4700) v1(5420,4700) v1(5500,4700) v1(5580,4700) v1(5660,4700) v1(5740,4700) v1(5820,4700) v1(5900,4700) v1(5980,4700) v1(6060,4700) v1(6140,4700) v1(6220,4700) v1(6300,4700) v1(6380,4700) v1(6460,4700) v1(6540,4700) v1(6620,4700) v1(6700,4700) v1(6780,4700) v1(6860,4700) v1(6940,4700) v1(7020,4700) v1(7100,4700) v1(7180,4700) v1(7260,4700) v1(7340,4700) v1(7420,4700) v1(7500,4700) v1(7580,4700) v1(7660,4700) v1(7740,4700) v1(7820,4700) v1(7900,4700) v1(7980,4700) v1(8060,4700) v1(8140,4700) v1(8220,4700) v1(8300,4700) 8340,4700 ; v1(4600,2060) v1(4700,2060) 4700,1920 v1(4780,1920) ; 4600,2660 v1(4680,2660) 4700,2680 4700,2740 ; v1(4600,2740) 4700,2740 ; 4700,2740 v1(4700,2800) v1(4780,2800) ; v1(4780,1920) v1(4780,1880) v1(4840,1820) v1(4900,1760) v1(4960,1700) v1(5020,1640) v1(5060,1600) v1(5120,1600) v1(5180,1600) v1(5240,1600) v1(5300,1600) v1(5360,1600) v1(5420,1600) v1(5480,1600) v1(5520,1560) v1(5560,1520) v1(5620,1460) v1(5660,1420) v1(5720,1360) v1(5780,1300) v1(5840,1240) v1(5900,1180) v1(5960,1120) v1(6020,1060) pad.@6100,980 ; v1(4780,2800) v1(4780,2860) v1(4840,2920) ; v1(4840,2920) 5040,3120 ; 5040,3120 5460,3120 v1(5520,3180) ; 5040,3120 v1(5340,3420) ; v1(5340,3420) v1(5400,3360) v1(5460,3300) v1(5500,3260) 5520,3240 v1(5520,3180) ; v1(5520,3180) v1(5560,3220) v1(5600,3260) v1(5640,3300) v1(5700,3360) v1(5760,3420) v1(5820,3480) v1(5880,3540) v1(5940,3600) v1(6000,3660) v1(6200,3860) v1(6260,3920) v1(6320,3980) v1(6360,4020) v1(6420,4080) v1(6480,4140) v1(6540,4200) v1(6600,4260) v1(6660,4320) v1(6740,4400) v1(6820,4400) v1(6900,4400) v1(6980,4400) v1(7020,4400) ; pad.@6100,980 v1(6200,880) v1(6260,820) v1(6320,760) v1(6380,700) v1(6440,640) v1(6500,580) v1(6560,520) v1(6620,460) v1(6680,400) v1(6720,360) v1(6760,320) v1(6860,320) v1(6940,320) v1(7020,320) ; 6100,2360 v1(6120,2380) v1(6180,2440) v1(6240,2500) v1(6300,2560) v1(6360,2620) v1(6420,2680) v1(6460,2680) v1(6540,2680) v1(6620,2680) v1(6700,2680) v1(6780,2680) v1(6860,2680) v1(6940,2680) v1(7020,2680) ; 6100,2360 v1(6120,2340) v1(6180,2280) v1(6240,2220) v1(6300,2160) v1(6360,2100) v1(6420,2040) v1(6460,2040) v1(6540,2040) v1(6620,2040) v1(6700,2040) v1(6780,2040) v1(6860,2040) v1(6940,2040) v1(7020,2040) ; v1(7020,320) v1(7020,400) v1(7020,460) v1(7020,540) v1(7020,620) v1(7020,700) v1(7020,780) v1(7020,860) v1(7020,940) v1(7020,1020) v1(7020,1100) v1(7020,1180) ; v1(7020,320) v1(7100,320) v1(7180,320) v1(7260,320) v1(7340,320) v1(7420,320) v1(7500,320) v1(7580,320) v1(7664.72,320) v1(7740,320) v1(7820,320) 7840,320 ; v1(7020,1180) v1(7020,1260) v1(7020,1340) v1(7020,1420) v1(7020,1500) v1(7020,1560) v1(7020,1640) v1(7020,1720) v1(7020,1800) v1(7020,1880) v1(7020,1960) v1(7020,2040) ; v1(7020,2680) v1(7020,2780) v1(7020,2860) v1(7020,2940) v1(7020,3020) v1(7020,3100) v1(7020,3180) v1(7020,3260) v1(7020,3380) v1(7020,3460) v1(7020,3540) ; v1(7020,2680) v1(7100,2680) v1(7180,2680) v1(7260,2680) v1(7340,2680) v1(7420,2680) v1(7500,2680) v1(7580,2680) v1(7660,2680) v1(7740,2680) v1(7820,2680) 7840.28,2680 ; v1(7020,3540) v1(7020,3760) v1(7020,3840) v1(7020,3920) v1(7020,4000) v1(7020,4080) v1(7020,4160) v1(7020,4240) v1(7020,4320) v1(7020,4400) ; v1(7020,4400) v1(7060,4400) v1(7140,4400) v1(7220,4400) v1(7300,4400) v1(7380,4400) v1(7460,4400) v1(7540,4400) v1(7620,4400) v1(7700,4400) v1(7780,4400) 7840,4400 ; 8340,24 v1(8380,24) v1(8460,24) v1(8540,24) v1(8620,24) v1(8700,24) v1(8780,24) v1(8860,24) ; v1(8340,2360) 9020,2360
  Bottom Layer w10: 4280,2380 v1(4280,2347.5) ; v1(4320,2322.5) v1(4300,2322.5) ; v1(4320,2347.5) v1(4300,2347.5) ; 4520,2270 4570.15,2270 4570.53,2270.37 4729.63,2270.37 v1(4730,2270) ; 4520,2346.25 4521.25,2347.5 v1(4560,2347.5) ; 4520,2380 4527.5,2372.5 v1(4560,2372.5) ; 4520,2460 4530.37,2449.63 4729.63,2449.63 v1(4730,2450) ; v1(4280,2347.5) v1(4300,2347.5) ; v1(4280,2347.5) v1(4280,2322.5) v1(4300,2322.5) ; v1(4300,2322.5) v1(4300,2347.5) ; v1(4560,2347.5) v1(4580,2347.5) ; v1(4560,2347.5) v1(4560,2372.5) ; v1(4560,2372.5) v1(4580,2372.5) ; v1(4580,2347.5) v1(4600,2347.5) ; v1(4580,2347.5) v1(4580,2372.5) ; v1(4580,2372.5) v1(4600,2372.5) ; v1(4600,2347.5) v1(4620,2347.5) 4620,2360 v1(4620,2372.5) v1(4600,2372.5) ; v1(4600,2347.5) v1(4600,2372.5)
  Bottom Layer w20: v1(180,2420) 180,2140 v1(200,2120) ; 540,2580 530.04,2580 520.52,2570.47 469.53,2570.47 440,2600 440,2680 540,2780 880,2780 ; v1(580,1220) 620,1260 v1(660,1260) ; J9.3@600,2120 700,2120 780,2200 v1(1260,2200) v1(1500,2200) ; J9.7@600,2320 1140,2320 v1(1140,2280) 1300,2280 ; v1(700,2420) v1(900,2420) v1(1140,2420) 1400,2420 v1(1420,2440) 1518.99,2440 1527.99,2449 1552.01,2449 1580,2421.01 v1(1580,2400) 1580,2360 ; v1(700,2500) 700,2527.87 ; v1(760,660) 760,760 v1(780,780) ; J16.3@840,940 780,940 v1(780,780) ; v1(860,400) 920,460 v1(940,460) 980,460 ; 900,980 v1(900,1200) v1(780,1200) 780,980 980,980 ; v1(1100,120) v1(1100,200) 1100,240 ; v1(1120,420) 1140,420 ; 1140,1120 v1(1180,1120) ; v1(1140,1500) 1120,1480 ; v1(1240,1340) 1220,1340 ; v1(1300,2320) 1300,2280 ; v1(1400,3180) v1(1500,3180) ; v1(1480,2400) 1480,2440 ; v1(1520,2900) 1560,2900 1580,2880 ; v1(1560,1040) 1580,1040 ; v1(1680,880) 1680,900 1690.22,910.22 ; v1(1720,2900) v1(1720,2960) ; v1(1740,960) 1690.22,910.22 ; 2360,300 2360,380 2201.01,380 1996.87,584.14 1996.87,603.56 1690.22,910.22 ; J11.3@2400,300 2349.96,300 2349.96,180 2379.48,150.47 2460,150.47 v1(2460,24) v1(2380,24) v1(2300,24) 2300,118.99 2291,127.99 2291,229 v1(2269.53,250.47) 2180,250.47 2180,318.99 1708.52,790.47 1570.47,790.47 1570.47,900 1580,909.53 1580,1040 ; 2400,2620 1820,2620 v1(1720,2720) 1660,2720 ; pad.@3051.18,3838.58 3051.18,3648.82 v1(3060,3640) ; 3480,1720 v1(3120,2080) v1(3060,2140) 3000,2200 ; 3900,2080 3760,2080 v1(3500,2340) v1(3440,2400) v1(3380,2460) v1(3300,2540) 3380,2620 v1(3460,2540) v1(3520,2480) v1(3580,2420) 3840,2160 v1@3900,2160 ; v1(3980,2240) 4028.5,2240 ; v1(3980,2320) 4028.5,2320 4028.5,2240 ; v1(3980,2400) R49.1@4028.5,2400 ; v1(3980,2500) C60.2@4028.5,2500 ; 4028.5,2180 4180,2180 ; C44.1@4028.5,2331.5 R49.1@4028.5,2400 ; C42.2@4028.5,2565.45 C60.2@4028.5,2506.26 C60.2@4028.5,2500 ; C42.2@4031.5,2565.45 4031.5,2611.5 4060,2640 v1(4140,2640) ; v1(4220,360) 4260,320 v1(4260,280) 4260,240 v1(4300,200) ; v1(4240,1980) 4280,1980 v1(4280,1820) 4280,1740 v1(4360,1740) ; v1(4280,2322.5) 4280,2220 ; 4281.65,1981.65 4280,1983.29 v1(4280,2170) 4280,2216.71 4281.65,2218.35 4280,2220 ; v1(4320,2322.5) v1(4320,2347.5) ; v1(4420,2322.5) v1(4420,2347.5) ; v1(4420,2420) 4360,2420 ; v1(4420,2520) 4360,2520 ; v1(4440,580) 4480,540 v1(4520,540) 4560,540 v1(4600,500) ; v1(4480,2460) 4520,2460 ; 4520,2346.25 4520,2270 4520,2240 ; 4522.5,2172.5 4520,2170 ; 4620,2360 v1(4720,2360) ; C38.2@4840,2140 4840,2180 ; C39.2@4840,2580 4840,2540 ; C36.2@4980,2140 4980,2180 ; C37.2@4980,2580 4980,2540 ; pad.@6003.94,885.83 pad.@6108.17,885.83 ; v1(8290,4400) v1(8380,4400) ; v1(8300,320) v1(8380,320) ; v1(8300,2040) v1(8380,2040) ; v1(8300,2680) v1(8380,2680) ; 700,2527.87 688.45,2527.87 680.58,2520 J9.11@600,2520 550.47,2569.53 550.47,2669.53 580,2699.06 v1(580,2700) v1(880,2700) ; 700,2527.87 711.55,2527.87 719.42,2520 v1(880,2520) 1060,2520 ; v1(780,780) v1(900,780) 980,780 ; v1(880,2700) 880,2780 ; v1(880,2700) 880,2620 980,2620 980,2860 1040,2860 ; 880,2780 880,2980 980,3080 v1(2320,3080) 2400,3080 2400,3000 v1(2320,3000) 1640,3000 ; 980,460 v1(980,380) v1(980,320) 980,280 1000,260 v1(1030,260) 1080,260 1100,240 ; 980,460 v1(980,540) v1(980,580) v1(980,660) 980,780 ; 980,780 v1(980,940) 980,980 ; 980,980 980,1120 940,1160 v1(940,1300) 940,1400 v1(960,1420) 1040,1500 v1(1080,1500) 1100,1500 1120,1480 ; 1040,2860 v1(1040,3000) 1200,3000 1200,2980 ; 1040,2860 1060,2860 ; 1060,2520 1060,2600 1680,2600 1760,2520 v1(2320,2520) 2400,2520 2400,2440 ; 1060,2520 v1(1520,2520) 1640,2520 v1(1720,2440) v1(2320,2440) 2400,2440 ; 1060,2780 1360,2780 1400,2820 v1(1420,2820) 1520,2820 1560,2780 1560,2741.01 1520,2701.01 v1(1520,2700) ; 1060,2780 1060,2700 v1(1140,2700) v1(1268.5,2700) v1(1520,2700) ; 1060,2780 1060,2860 ; 1060,2860 1200,2860 1200,2980 ; 1100,240 1140,280 1140,340 ; 1120,1280 1120,1480 ; 1120,1280 1060,1220 v1(1060,960) v1(1060,740) 1060,680 v1(1080,660) 1140,600 v1(1140,460) 1140,420 ; 1120,1280 v1(1140,1300) 1180,1340 1220,1340 ; 1140,340 1140,420 ; 1140,340 v1(1200,280) 1360,120 v1(1440,120) 1940,120 v1(1940,160) 1940,200 v1(1740,200) 1400,200 v1(1220,380) v1(1220,500) v1(1220,740) ; v1(1140,900) 1140,1140 1220,1220 v1(1220,1240) 1220,1340 ; v1(1140,900) v1(1140,740) v1(1220,740) ; v1(1140,900) 1220,900 v1(1220,740) ; 1200,2980 v1(1240,2980) 1260,3000 v1(1560,3000) 1640,3000 ; 1300,2280 1518.99,2280 1527.99,2271 1552.01,2271 1561.01,2280 1580,2280 ; v1(1500,2040) 1500,2100 ; v1(1500,2040) 1640,1900 1640,1860 1600,1820 1560,1820 1400,1980 v1(1260,1980) 1140,1980 v1(1140,2000) 1140,2100 v1(1260,2100) v1(1380,2100) 1500,2100 ; v1(1500,2040) 1518.99,2040 1527.99,2031 1552.01,2031 1561.01,2040 1580,2040 ; 1500,2100 v1(1500,2200) ; v1(1500,2200) 1518.99,2200 1527.99,2209 1552.01,2209 1580,2181.01 v1(1580,2160) v1(1580,2080) 1580,2040 ; v1(1520,1680) v1(1520,1420) 1520,1340 1440,1340 1440,1680 v1(1520,1680) ; v1(1520,1680) 1520,1720 ; 1520,1720 1600,1720 1600,1800 1180,1800 1180,1720 1520,1720 ; v1(1520,2700) 1520,2680 1529,2671 1611,2671 1660,2720 ; 1580,1040 1580,1220 1660,1220 v1(1660,1140) 1660,940.43 1690.22,910.22 ; 1580,2040 v1(1720,2040) v1(1720,2140) v1(2320,2140) 2400,2140 2400,2220 v1(2320,2220) v1(1720,2220) 1660,2220 1600,2280 1580,2280 ; 1580,2280 v1(1580,2320) 1580,2360 ; 1580,2360 v1(1720,2360) v1(2320,2360) 2400,2360 2400,2440 ; 1580,2880 1640,2940 1640,3000 ; 1580,2880 v1(1660,2800) 1660,2720 ; v1(2380,1700) 2380,1620 v1(2460,1620) ; v1(2380,1700) v1(2620,1700) 2660,1700 ; v1(2380,1700) 2380,1800 2660,1800 2660,1700 ; v1(2460,1620) 2460,1360 2260,1160 2260,1060 2360,1060 v1(2480,1180) 2580,1280 2580,1620 ; v1(2460,1620) 2580,1620 ; 2580,1620 v1(2620,1620) 2680,1620 2680,1700 2660,1700 ; v1(2940,2140) v1(3000,2080) v1(3060,2020) 3420,1660 3540,1780 v1(3480,1840) v1(3420,1900) v1(3360,1960) v1(3300,2020) v1(3240,2080) v1(3180,2140) v1(3120,2200) v1(3060,2260) ; v1(2940,2140) 3000,2200 ; v1(2940,2140) 2880,2200 3060,2380 3120,2320 v1(3060,2260) ; 3000,2200 v1(3060,2260) ; v1@3900,2160 v1(3900,2240) v1(3900,2320) v1(3900,2400) v1(3900,2480) v1(3900,2560) v1(3900,2640) 3900,2740 4140,2740 v1(4140,2640) ; v1@3900,2160 v1(3901.01,2160) 3900,2158.99 3900,1900 v1(4040,1900) 4120,1900 4120,2060 ; 4028.5,2240 C65.2@4028.5,2140 4028.5,2060 v1(4100,2060) 4120,2060 ; R49.1@4028.5,2400 R49.1@4028.5,2403.13 4028.5,2460 ; 4028.5,2460 4140,2460 ; 4028.5,2460 C60.2@4028.5,2500 ; 4120,2060 4180,2060 4180,2180 ; 4140,2460 v1(4140,2640) ; 4140,2460 4150,2450 v1(4180,2450) 4180,2180 ; 4280,2220 4360,2220 ; v1(4320,2347.5) 4320,2380 ; v1(4320,2347.5) v1(4420,2347.5) ; 4320,2380 4360,2380 4360,2420 ; 4320,2380 4240,2380 v1(4240,2640) 4240,2780 4260,2800 v1(4280,2800) 4300,2800 4320,2780 4320,2740 v1(4400,2740) v1(4400,2660) 4380,2660 4360,2640 4360,2580 ; v1(4360,1740) v1(4360,1820) v1(4360,2060) 4360,2220 ; v1(4360,1740) v1(4440,1740) v1(4440,1820) v1(4440,2035.77) v1(4440,2100) v1(4520,2100) ; 4360,2220 4380,2240 v1(4440,2240) 4520,2240 ; 4360,2420 4360,2520 ; 4360,2520 4360,2580 ; 4360,2580 4367.5,2572.5 v1(4420,2572.5) 4427.5,2580 v1(4460,2580) 4520,2580 ; v1(4420,2347.5) v1(4440,2347.5) 4520,2347.5 4520,2380 4520,2460 ; v1(4520,2100) 4560,2100 v1(4600,2060) v1(4700,2060) 4700,2020 ; v1(4520,2100) 4520,2140 ; 4520,2140 4572.5,2140 v1(4580,2147.5) v1(4580,2172.5) v1(4600,2172.5) v1(4620,2172.5) v1(4720,2172.5) v1(4740,2172.5) v1(4760,2172.5) 4767.5,2180 4840,2180 ; 4520,2140 4520,2170 ; 4520,2170 4520,2240 ; 4520,2460 4520,2580 ; 4520,2580 4572.5,2580 ; 4572.5,2580 v1(4580,2572.5) v1(4580,2547.5) v1(4600,2547.5) v1(4620,2547.5) v1(4720,2547.5) v1(4740,2547.5) v1(4760,2547.5) 4767.5,2540 4840,2540 ; 4572.5,2580 4572.5,2652.5 4580,2660 v1(4680,2660) 4700,2680 4700,2700 ; 4700,2020 4700,1920 v1(4780,1920) 4800,1900 4880,1900 ; 4700,2020 v1(4780,2020) 4782.62,2017.38 4880,2017.38 ; 4700,2700 v1(4700,2800) v1(4780,2800) 4800,2820 4880,2820 ; 4700,2700 v1(4780,2700) 4782.62,2702.62 4880,2702.62 ; 4840,2180 v1(4900,2180) ; 4840,2540 v1(4900,2540) ; 4880,1900 4880,2017.38 ; 4880,1900 5000,1900 5000,2017.38 ; 4880,2017.38 4880,2100 4900,2120 v1(4900,2180) ; 4880,2017.38 5000,2017.38 ; 4880,2702.62 4880,2620 4900,2600 v1(4900,2540) ; 4880,2702.62 4880,2820 ; 4880,2702.62 5057.38,2702.62 v1(5060,2700) ; 4880,2820 4941.01,2820 ; v1(4900,2180) 4980,2180 ; v1(4900,2540) 4980,2540 ; 4941.01,2820 4841.01,2920 v1(4840,2920) v1(4820,2940) v1(4780,2980) v1(4740,3020) v1(5240,3520) v1(5280,3480) v1(5340,3420) v1(5400,3360) v1(5460,3300) v1(5500,3260) 5520,3240 v1(5520,3180) 5520,2420 v1(5460,2360) 5280,2180 5140,2180 ; 4941.01,2820 5060,2701.01 v1(5060,2700) ; 4980,2180 5140,2180 ; 4980,2540 5020,2540 5080,2600 5080,2680 v1(5060,2700) ; 5000,2017.38 5057.38,2017.38 v1(5060,2020) 5140,2020 5140,2180 ; 360,860 v1(360,920) 360,960 380,980 v1(460,980) 560,980 580,960 v1(580,940) 580,880 v1(578.9,878.9) 578.9,858.9 560,840 v1(460,840) 380,840 360,860 ; 360,1700 v1(360,1760) 360,1800 380,1820 560,1820 v1(580,1800) v1(580,1680) v1(460,1680) 380,1680 360,1700
  other v1: 2480,200 1500,300 2160,340 1840,431 1600,460 1940,560 2020,560 2400,940 25.58,1020 1860,1120 1940,1120 2360,1260 2460,1420 2580,1420 4520,1660 1260,1720 1000,1800 2580,1800 1260,1820 2060,1820 260,1840 1520,1860 3900,2000 780,2060 3680,2160 2880,2220 3620,2220 1000,2280 1380,2280 3560,2280 3700,2300 3000,2320 3640,2360 2840,2440 2840,2520 1060,2560 360,2720 440,2720 4240,2720 580,2780 3300,2800 3780,2800 680,2860 880,2860 3300,2880 3780,2880 3300,2960 3780,2960 800,2980 680,3200 1260,3260 1320,3260 1400,3260 1480,3260 1520,3260 680,3280 1181.01,3320 1620,3320 220,3340 300,3340 380,3340 460,3340 540,3340 620,3340 1181.01,3400 1620,3400 1181.01,3440 1620,3480 620,3500 660,3500 700,3500 780,3500 820,3500 860,3500 25.58,3520 580,3540 740,3540 900,3540 580,3580 740,3580 900,3580 1620,3580 580,3620 740,3620 900,3620 2400,3640 2480,3640 2560,3640 620,3660 660,3660 700,3660 780,3660 820,3660 860,3660 1620,3660 860,3700 1620,3700 820,3740 1620,3820 780,3840 580,3900 660,3900 1181.01,3900 1620,3900 1181.01,3980 1620,3980 1181.01,4060 1620,4060 1180,4140 1620,4140 1180,4220 1620,4220 3360,4300 760,4700 840,4700 920,4700 1001.01,4700 1081.01,4700
GVDD_AB: R42.1 U1.1 | length 364.7
  Top Layer w10: v1(4080,2680) 4240,2680 4297.5,2622.5 U1.1@4372.36,2622.5
  Bottom Layer w20: R42.1@4031.5,2680 v1(4080,2680)
GVDD_CD: R48.1 U1.22 | length 397.8
  Top Layer w10: v1(4080,1960) 4180,1960 4317.5,2097.5 U1.22@4372.36,2097.5
  Bottom Layer w20: R48.1@4031.5,1960 v1(4080,1960)
In_L: J7.2 J16.1 R12.2 R17.1 | length 1041.5
  Top Layer w20: J7.2@472.44,1748.66 571.34,1748.66 620,1700 620,1500 ; R17.1@680,1452.99 678.5,1454.49 678.5,1501.5 ; R12.2@688.5,1541.5 688.5,1511.5 678.5,1501.5 ; J16.1@840,1140 720,1140 620,1240 620,1500 ; 620,1500 677.01,1500 678.5,1501.5
In_R: J8.2 J16.4 R29.2 R34.1 | length 675
  Top Layer w20: J8.2@472.44,908.66 651.34,908.66 680,880 680,840 ; R34.1@680,612.99 680,661.5 688.5,670 R29.2@688.5,701.5 ; R29.2@688.5,700 R29.2@688.5,701.5 ; J16.4@860,840 680,840 ; 680,840 680,760 688.5,751.5 R29.2@688.5,701.5
INPUT_A: R63.1 U1.5 | length 3026
  Top Layer w10: 4242.5,2522.5 U1.5@4372.36,2522.5
  Top Layer w20: R63.1@1802.99,1500 1842.99,1460 2680,1460 3660,2440 4000,2440 4082.5,2522.5 4242.5,2522.5
INPUT_B: R64.1 U1.6 | length 3297.5
  Top Layer w10: 4240,2480 4257.5,2497.5 U1.6@4372.36,2497.5
  Top Layer w20: R64.1@1800,1040 1800,1220 1960,1380 2720,1380 3700,2360 4000,2360 4020,2380 4020,2400 4100,2480 4240,2480 ; R64.1@1800,1042.99 R64.1@1802.99,1040
INPUT_C: R1.2 R65.1 U1.16 | length 3631.5
  Top Layer w10: R65.1@1800,662.99 R65.1@1802.99,660 ; 4280,2240 4287.5,2247.5 U1.16@4372.36,2247.5
  Top Layer w20: R1.2@1791.5,840 1791.5,768.5 1802.99,757.01 ; R65.1@1802.99,660 1802.99,757.01 ; 4280,2240 4040,2240 4000,2280 3740,2280 2760,1300 2000,1300 1900,1200 1900,820 1837.01,757.01 1802.99,757.01
INPUT_D: R8.1 R66.1 U1.17 | length 3918.5
  Top Layer w10: 4280,2200 4302.5,2222.5 U1.17@4372.36,2222.5
  Top Layer w20: R8.1@1791.5,380 1791.5,369.75 1820,341.25 ; 1799.38,320.62 1820,341.25 ; 1800,320 1800,202.99 R66.1@1802.99,200 ; 4280,2200 3780,2200 2800,1220 2040,1220 1980,1160 1980,501.25 1820,341.25
M2: J11.2 U1.4 | length 4457.4
  Top Layer w10: U1.4@4372.36,2547.5 4440,2547.5
  Top Layer w20: J11.2@2380,200 2420,240 4280,240 4560,520 4560,2120 4520,2160 4520,2467.5 4440,2547.5
NetC1_1: C1.1 C2.2 R3.1 R14.2 U2.1 | length 767.3
  Top Layer w20: R14.2@900,1332.99 1150,1332.99 1175,1357.99 1175,1537.99 1171.5,1541.5 C2.2@1171.5,1620 C2.2@1171.5,1621.5 ; R3.1@1171.5,1540 C1.1@1380.63,1540 C1.1@1388.5,1540
NetC1_2: C1.2 R2.2 | length 77
  Top Layer w20: C1.2@1451.5,1540 C1.2@1459.37,1540 R2.2@1528.5,1540
NetC2_1: C2.1 R3.2 R13.1 U2.2 | length 297.5
  Top Layer w20: R13.1@1031.5,1541.5 R3.2@1108.5,1541.5 ; C2.1@1108.5,1621.5 R3.2@1108.5,1541.5 ; U2.2@1125,1407.8 1125,1475 1108.5,1491.5 R3.2@1108.5,1541.5
NetC3_1: C3.1 R9.2 R14.1 U2.6 | length 431.6
  Top Layer w20: R14.1@900,1270 1050,1270 1075,1245 1075,1087.99 1068.5,1081.5 C3.1@1068.5,1001.5
NetC3_2: C3.2 C12.1 R9.1 U2.7 | length 445.5
  Top Layer w20: U2.7@1125,1195.2 1125,1087.99 1131.5,1081.5 C3.2@1131.5,1001.5 ; R9.1@1131.5,1080 C12.1@1380.63,1080
NetC4_1: C4.1 R2.1 R63.2 | length 168.5
  Top Layer w20: C4.1@1591.5,1461.5 1591.5,1501.5 ; R2.1@1591.5,1541.5 1591.5,1501.5 ; R63.2@1680,1501.5 1591.5,1501.5
NetC11_1: C11.1 C13.1 R12.1 | length 156.1
  Top Layer w20: R12.1@751.5,1541.5 818.5,1541.5 818.5,1454.49 C13.1@820,1452.99
NetC11_2: C11.2 R13.2 | length 77
  Top Layer w20: C11.2@891.5,1541.5 R13.2@968.5,1541.5
NetC12_2: C12.2 R16.2 | length 77
  Top Layer w20: C12.2@1451.5,1081.5 R16.2@1528.5,1081.5
NetC14_1: C14.1 R16.1 R64.2 | length 165.5
  Top Layer w20: C14.1@1591.5,1001.5 1591.5,1041.5 ; R16.1@1591.5,1081.5 1591.5,1041.5 ; R64.2@1677.01,1041.5 1591.5,1041.5
NetC15_1: C15.1 C18.2 R26.1 R31.2 U3.1 | length 760.9
  Top Layer w20: R31.2@900,492.99 1151.5,492.99 1175,516.5 1175,697.99 1171.5,701.5 1171.5,781.5 C18.2@1172.99,780 ; R26.1@1172.99,700 C15.1@1380.63,700
NetC15_2: C15.2 R24.2 | length 77
  Top Layer w20: C15.2@1451.5,701.5 R24.2@1528.5,701.5
NetC18_1: C18.1 R26.2 R30.1 U3.2 | length 297.5
  Top Layer w20: R30.1@1031.5,701.5 R26.2@1108.5,701.5 ; C18.1@1108.5,781.5 R26.2@1108.5,701.5 ; U3.2@1125,567.79 1125,636.5 1108.5,652.99 R26.2@1108.5,701.5
NetC19_1: C19.1 R28.2 R31.1 U3.6 | length 432.4
  Top Layer w20: R31.1@900,430 1051.5,430 1075,406.5 1075,247.99 1068.5,241.49 C19.1@1068.5,161.5
NetC19_2: C19.2 C23.1 R28.1 U3.7 | length 445.5
  Top Layer w20: U3.7@1125,355.2 1125,247.99 1131.5,241.5 C19.2@1131.5,161.5 ; R28.1@1131.5,240 C23.1@1380.63,240
NetC20_1: C20.1 R24.1 R65.2 | length 165.5
  Top Layer w20: C20.1@1591.5,621.5 1591.5,661.5 ; R24.1@1591.5,701.5 1591.5,661.5 ; R65.2@1677.01,661.5 1591.5,661.5
NetC22_1: C22.1 C24.1 R29.1 | length 169
  Top Layer w20: R29.1@751.5,701.5 828.5,701.5 820,692.99 C24.1@820,612.99
NetC22_2: C22.2 R30.2 | length 77
  Top Layer w20: C22.2@891.5,701.5 R30.2@968.5,701.5
NetC23_2: C23.2 R32.2 | length 77
  Top Layer w20: C23.2@1451.5,241.5 R32.2@1528.5,241.5
NetC25_1: C25.1 R32.1 R66.2 | length 148.5
  Top Layer w20: C25.1@1591.5,161.5 1591.5,201.5 ; R32.1@1591.5,241.5 1591.5,201.5 ; R66.2@1660,201.5 1591.5,201.5
NetC27_1: C27.1 C28.1 C29.1 J3.1 L2.2
NetC27_2: C27.2 R41.1 | length 147
  Top Layer w30: C27.2@8340,4421.5 R41.1@8340,4568.5
NetC30_1: C30.1 U7.4 | length 103.6
  Top Layer w20: C30.1@1320.63,1760 1320.63,1860.24 U7.4@1322.99,1862.6
NetC40_1: C40.1 L3.2 U1.35 | length 137.2
  Bottom Layer w20: C40.1@4919.37,2660 5000,2660 v1(5040,2620)
NetC40_2: C40.2 U1.43 | length 202.4
  Top Layer w10: U1.43@4665.14,2600 U1.43@4667.64,2597.5 4717.5,2597.5 v1(4740,2620)
  Bottom Layer w20: v1(4740,2620) 4780,2660 C40.2@4840.63,2660
NetC41_1: C41.1 L2.1 U1.39 U1.40 | length 65.6
  Top Layer w10: U1.39@4667.64,2497.5 U1.40@4667.64,2522.5
  Bottom Layer w20: C41.1@4919.37,2760 v1(4960,2760)
NetC41_2: C41.2 U1.44 | length 288.5
  Top Layer w10: U1.44@4667.64,2622.5 4702.5,2622.5 4740,2660 v1(4740,2760)
  Bottom Layer w20: v1(4740,2760) C41.2@4840.63,2760
NetC43_1: C43.1 C45.1 C46.1 J4.1 L3.1
NetC43_2: C43.2 R46.1 | length 147
  Top Layer w30: R46.1@8340,2511.5 C43.2@8340,2658.5
NetC44_2: C44.2 U1.11 | length 300.8
  Top Layer w10: v1@4140,2380.63 4309.74,2380.63 4317.87,2372.5 U1.11@4372.36,2372.5
  Bottom Layer w10: C44.2@4091.5,2340 4100,2340 v1(4140,2380)
NetC49_2: C49.2 U1.14 | length 306.8
  Top Layer w10: v1(4140,2320) 4162.5,2297.5 U1.14@4372.36,2297.5
  Bottom Layer w10: C49.2@4091.5,2280 4100,2280 v1(4140,2320)
NetC51_1: C51.1 U1.24 | length 198.9
  Top Layer w10: U1.24@4667.64,2122.5 4717.5,2122.5 v1(4740,2100)
  Bottom Layer w20: v1(4740,2100) 4780,2060 C51.1@4840.63,2060
NetC51_2: C51.2 L5.1 U1.32 | length 180.6
  Bottom Layer w20: C51.2@4919.37,2060 v1(5100,2060)
NetC52_1: C52.1 U1.23 | length 288.5
  Top Layer w10: U1.23@4667.64,2097.5 4702.5,2097.5 4740,2060 v1(4740,1960)
  Bottom Layer w20: v1(4740,1960) C52.1@4840.63,1960
NetC52_2: C52.2 L7.2 U1.27 U1.28 | length 65.6
  Top Layer w10: U1.27@4667.64,2197.5 U1.28@4667.64,2222.5
  Bottom Layer w20: C52.2@4919.37,1960 v1(4960,1960)
NetC53_1: C53.1 C54.1 C55.1 J5.1 L5.2
NetC53_2: C53.2 R51.1 | length 147
  Top Layer w30: C53.2@8340,2061.5 R51.1@8340,2208.5
NetC65_1: C65.1 U1.20 | length 284.5
  Top Layer w10: v1@4140,2138.76 4291.12,2138.76 4299.87,2147.5 U1.20@4372.36,2147.5
  Bottom Layer w20: C65.1@4091.5,2140 v1(4140,2140)
NetC66_1: C66.1 C68.1 C69.1 J6.1 L7.1
NetC66_2: C66.2 R55.1 | length 147
  Top Layer w30: R55.1@8340,151.5 C66.2@8340,298.5
NetC67_2: C67.2 U1.15 | length 332.3
  Top Layer w10: v1(4140,2280) 4145,2280 4152.5,2272.5 U1.15@4372.36,2272.5
  Bottom Layer w10: C67.2@4091.5,2220 4120,2220 4140,2240 v1(4140,2280)
NetD1_1: D1.1 Q1.2 R5.2 | length 198.7
  Top Layer w20: R5.2@1331.5,2280 D1.1@1331.5,2400 1334.8,2403.31 Q1.2@1408.82,2403.31
NetD2_1: D2.1 Q2.2 R7.2 | length 198.7
  Top Layer w20: R7.2@1331.5,2040 D2.1@1331.5,2160 1334.8,2163.31 Q2.2@1408.82,2163.31
NetD3_1: D3.1 R20.2 | length 77
  Top Layer w20: D3.1@1331.5,2760 R20.2@1408.5,2760
NetD4_1: D4.1 R21.2 | length 77
  Top Layer w20: D4.1@1331.5,2640 R21.2@1408.5,2640
NetD5_1: D5.1 R22.2 | length 77
  Top Layer w20: D5.1@1331.5,2520 R22.2@1408.5,2520
NetD6_2: D6.2 D7.2 F1.2 R43.1 R44.1
NetD8_K: D8.2 D9.2 F2.2 L4.1 | length 557.6
  Top Layer w50: D8.2@660,3413.39 D9.2@820,3413.39 820,3100.64 L4.1@760,3040.64
NetJ10_2: J10.2 R1.1 | length 340.1
  Top Layer w20: J10.2@1520,840 1520,900 1540,920 1700,920 1728.5,891.5 R1.1@1728.5,840
NetJ12_1: J12.1 R57.2 | length 128.5
  Top Layer w20: R57.2@2111.5,100 J12.1@2240,100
